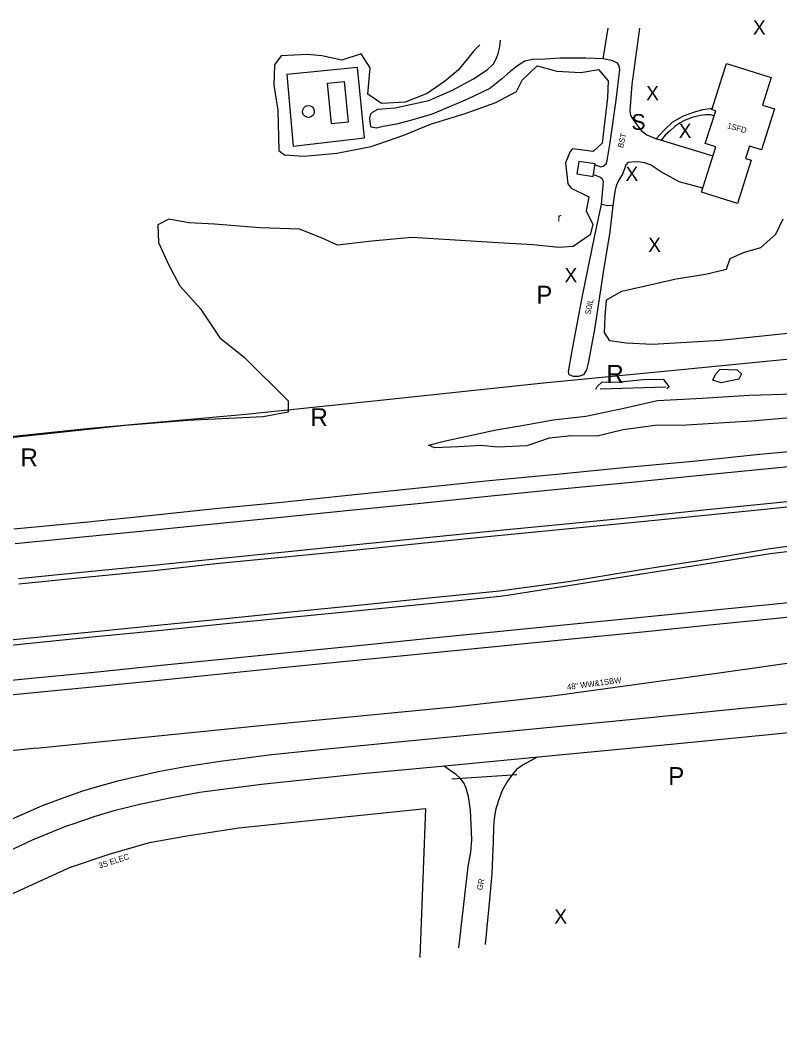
# Model space of a CAD drawing. Extents: x 2030130 to 2036320, y 723205 to 762423.
# Drawn here: x 2034070 to 2034598, y 726727 to 727435 of the extents above; entities that cross this region are included whole.
import ezdxf

# ---------------------------------------------------------------- set-up
doc = ezdxf.new("R2010")
doc.units = 0
for name, color, linetype in [('Draft_Bearing Label', 7, 'Continuous'), ('Draft_Station Cardinal Points', 7, 'Continuous'), ('Draft_Station Labels Major', 7, 'Continuous'), ('Draft_Station Tics Major', 7, 'Continuous'), ('Draft_Station Tics Minor', 7, 'Continuous'), ('Exist Terrain Model Ground Surface', 7, 'Continuous'), ('Old_Level_23', 7, 'Continuous'), ('Old_Level_28', 7, 'Continuous'), ('Prop Horizontal Alignment Ramp', 7, 'Continuous')]:
    doc.layers.add(name, color=color, linetype=linetype)

msp = doc.modelspace()

# ---------------------------------------------------------------- linework, layer by layer
at = {"layer": 'Draft_Station Labels Major'}
for points in [[(2034469.85, 727334.14), (2034473.89, 727332.82), (2034475.44, 727333.2), (2034476.51, 727333.91), (2034477.55, 727334.81), (2034478.22, 727337.13), (2034480.32, 727349.72), (2034484.5, 727379.19), (2034487.2, 727400.43), (2034486.69, 727402.99), (2034485.5, 727404.89), (2034483.25, 727406.08), (2034481.25, 727406.73), (2034475.4, 727408), (2034478.99, 727429.28)], [(2034500.85, 727429.34), (2034495.5, 727390.07), (2034493.98, 727371.73), (2034494.45, 727368.46), (2034496.4, 727365.63), (2034498.5, 727362.56), (2034502.07, 727357.95), (2034505.96, 727354.91), (2034511.95, 727352.45), (2034517.46, 727350.76), (2034551.97, 727340.32)], [(2034475.4, 727408), (2034463.47, 727408.38), (2034445.57, 727408.36), (2034435.16, 727407.79), (2034426.24, 727407.52), (2034421.06, 727406.44), (2034416.49, 727403.64), (2034410.78, 727399.1), (2034404.72, 727393.76), (2034396.55, 727387.38), (2034381.12, 727379.8), (2034356.45, 727369.36), (2034341.31, 727365.07), (2034331.58, 727362.53), (2034322.33, 727360.82), (2034317.62, 727359.67), (2034313.95, 727360.37), (2034313.38, 727362.41), (2034313.08, 727366.4), (2034313.76, 727369.74), (2034314.83, 727370.9), (2034318.68, 727372.84), (2034330.57, 727373.91), (2034354.06, 727378.91), (2034370.63, 727386.12), (2034385.13, 727393.97), (2034394.64, 727400.38), (2034399.24, 727404.53), (2034401.24, 727408.55), (2034402.26, 727411.74), (2034403.42, 727416.36), (2034404, 727420.97)], [(2034544.84, 727317.77), (2034528.38, 727322.25), (2034515.34, 727329.54), (2034508.45, 727334.06), (2034504.18, 727335.52), (2034500.08, 727336.16), (2034495.36, 727336.03), (2034492.58, 727335.76), (2034491.39, 727334.01), (2034490.54, 727332.05), (2034488.87, 727327.5), (2034486.27, 727323.15), (2034484.49, 727319.42), (2034483.68, 727315.61), (2034482.32, 727305.86), (2034478.84, 727305.49), (2034474.38, 727306.48), (2034475.69, 727322.37), (2034474.88, 727324.25), (2034473.13, 727325.5), (2034470.96, 727326.52), (2034468.78, 727327.11)], [(2034482.32, 727305.86), (2034480.25, 727287.32), (2034475.64, 727260.8), (2034469.48, 727219.32), (2034465.13, 727195.9), (2034463.97, 727191.28), (2034461.72, 727187.74), (2034458.33, 727186.69), (2034454.83, 727186.58), (2034451.87, 727187.75), (2034451.47, 727190), (2034453.96, 727204.56), (2034460.99, 727241.61), (2034469.74, 727284.88), (2034474.38, 727306.48)], [(2034065.11, 727080.41), (2034114.18, 727085.18), (2034159.64, 727089.79), (2034205.29, 727094.58), (2034249.28, 727098.81), (2034298.01, 727103.82), (2034347.16, 727108.96), (2034396.1, 727113.99), (2034445.48, 727118.71), (2034494.51, 727123.53), (2034540.56, 727127.91), (2034584.47, 727132.47), (2034632.87, 727136.76), (2034676.94, 727141.51), (2034722.09, 727145.88), (2034766.08, 727150.11), (2034812.33, 727155.08), (2034858.21, 727159.84), (2034888.24, 727162.54), (2034901.82, 727164.97), (2034916.41, 727170.63), (2034924.74, 727177.21), (2034929.69, 727189.85), (2034928.36, 727204.72)], [(2034065.93, 727070.12), (2034115.2, 727074.96), (2034160.49, 727079.46), (2034206.49, 727084.03), (2034251, 727088.47), (2034299.16, 727093.36), (2034348.43, 727098.29), (2034397.49, 727103.32), (2034446.31, 727108.22), (2034495.24, 727113.02), (2034541.05, 727117.58), (2034585.89, 727121.96), (2034633.87, 727126.74)], [(2034068.46, 727041.99), (2034117, 727046.94), (2034162.54, 727051.49), (2034207.98, 727056.52), (2034253.92, 727060.83), (2034301.72, 727065.65), (2034351.04, 727070.6), (2034399.56, 727075.53), (2034447.29, 727080.16), (2034497.37, 727085.09), (2034544.15, 727089.69), (2034587.77, 727094.04), (2034634.61, 727098.91), (2034679.17, 727103.19), (2034723.67, 727107.78), (2034769.24, 727112.21), (2034815.05, 727116.68), (2034860.82, 727121.08), (2034907.36, 727125.6), (2034927.3, 727127.18), (2034954.39, 727123.96), (2034963.41, 727122.83), (2034968.23, 727121), (2034968.86, 727119.68)], [(2034068.39, 727045.81), (2034116.83, 727050.61), (2034162, 727055.1), (2034207.66, 727059.77), (2034253.91, 727064.46), (2034301.41, 727069.22), (2034350.05, 727074.07), (2034398.98, 727078.95), (2034446.91, 727083.71), (2034497.05, 727088.65), (2034543.32, 727093.34), (2034587.33, 727097.77), (2034633.71, 727102.43)], [(2034025.26, 726999.38), (2034074.09, 727004.22), (2034121.41, 727008.89), (2034167.51, 727013.49), (2034212.61, 727017.88), (2034257.74, 727022.58), (2034304.93, 727027.33), (2034354.43, 727032.28), (2034403.23, 727037.18), (2034451.44, 727043.68), (2034500.54, 727051.92), (2034548.23, 727059.39), (2034591.81, 727066.61), (2034638.18, 727072.74)], [(2034025.48, 726995.5), (2034074.11, 727000.46), (2034121.82, 727005.27), (2034167.82, 727009.9), (2034212.93, 727014.39), (2034258.03, 727018.87), (2034305.11, 727023.52), (2034354.59, 727028.47), (2034403.42, 727033.39), (2034410.21, 727034.33), (2034451.41, 727040.91), (2034500.85, 727048.75), (2034548.22, 727056.21), (2034591.76, 727063.29), (2034638.43, 727068.84)], [(2034307.24, 726999.43), (2034356.84, 727004.45), (2034406.28, 727009.3), (2034452.81, 727013.89), (2034502.16, 727018.82), (2034550.88, 727023.74), (2034595.46, 727028.17), (2034641.07, 727032.82), (2034684.61, 727037.18), (2034729.52, 727041.63), (2034774.89, 727046.13), (2034819.08, 727050.5), (2034865.64, 727055.21), (2034912.23, 727059.85), (2034960.25, 727064.7), (2035005.43, 727069.15)], [(2034029.29, 726961.54), (2034076.69, 726966.05), (2034124.58, 726970.8), (2034170.82, 726975.48), (2034215.97, 726980.04), (2034261.31, 726984.82), (2034308.3, 726989.33), (2034357.75, 726994.14), (2034407.05, 726999.09), (2034453.5, 727003.73), (2034502.96, 727008.69), (2034552.18, 727013.64), (2034596.47, 727018.1), (2034642.31, 727022.98), (2034686.47, 727027.2), (2034731.1, 727031.69), (2034775.53, 727036.01), (2034820.01, 727040.42), (2034866.86, 727045.17), (2034912.58, 727049.64), (2034961.1, 727054.42), (2035006.09, 727059.13)], [(2034028.47, 726971.41), (2034075.13, 726976.03), (2034123.42, 726980.84), (2034169.95, 726985.53), (2034214.61, 726990.05), (2034260.27, 726994.74), (2034307.24, 726999.43)], [(2034100.02, 726893.21), (2034113.19, 726897.73), (2034127.48, 726902.01), (2034138.45, 726904.91), (2034153.6, 726908.58), (2034166.83, 726911.5), (2034184.54, 726914.84), (2034208.76, 726918.46), (2034244.76, 726923.08), (2034281.05, 726926.95), (2034335.04, 726932.09), (2034407.37, 726939.15), (2034496.46, 726947.83), (2034567.94, 726954.98), (2034652.73, 726963.38), (2034739.31, 726971.94), (2034824.38, 726980.7), (2034903.5, 726988.86), (2034964.59, 726994.74)], [(2034965.29, 726974.83), (2034889.6, 726967.15), (2034805.97, 726958.77), (2034704.1, 726948.2), (2034616.57, 726939.46), (2034525.2, 726930.45), (2034442.43, 726922.42), (2034365.29, 726915.02), (2034307.64, 726909.57), (2034237.47, 726902.31), (2034194.3, 726896.56), (2034172.53, 726892.46), (2034152.78, 726888.36), (2034134.81, 726883.95), (2034120.78, 726879.64), (2034106.93, 726874.9), (2034101.08, 726873.01)], [(2034429.65, 726921.2), (2034419.87, 726915.98), (2034415.15, 726912.75), (2034411.9, 726908.66), (2034408.77, 726904.65), (2034405.23, 726898.14), (2034402.67, 726891.03), (2034400.63, 726884.43), (2034399.56, 726878.41), (2034399.1, 726872.66), (2034398.85, 726862.08), (2034398.37, 726851.73), (2034397.92, 726840.09), (2034396.44, 726822.11), (2034393.43, 726790.74)], [(2034375.08, 726788.34), (2034381.58, 726845.05), (2034383.34, 726854.98), (2034383.99, 726863.86), (2034383.67, 726874.37), (2034383.09, 726884.4), (2034381.61, 726893.86), (2034380.04, 726899.75), (2034378.48, 726903.51), (2034375.95, 726906.75), (2034373.18, 726909.26), (2034370.6, 726910.76), (2034364.65, 726914.96)], [(2033812.11, 726727.17), (2033828.95, 726734.67), (2033849.51, 726744.64), (2033871.89, 726757.68), (2033893.57, 726771.7), (2033914.82, 726786.38), (2033937.73, 726803.32), (2033961.25, 726820.08), (2033982.38, 726834.35), (2034000.03, 726845.41), (2034021.37, 726857.68), (2034043.29, 726868.71), (2034063.4, 726878.13), (2034085.11, 726887.6), (2034100.02, 726893.21)], [(2034101.08, 726873.01), (2034077.84, 726863.35), (2034051.94, 726851.31), (2034025.37, 726837.58), (2033999.28, 726821.86), (2033977.92, 726808.19), (2033952.29, 726788.94), (2033920.71, 726765.94), (2033902.13, 726753.17), (2033889.02, 726744.27), (2033873.65, 726735.09), (2033859.69, 726727.5)]]:
    msp.add_lwpolyline(points, dxfattribs=at)
at = {"layer": 'Draft_Station Tics Major'}
msp.add_line((2034519.18, 727179.08), (2034473.32, 727177.8), dxfattribs=at)
for points in [[(2034389.53, 727417.76), (2034385.49, 727413.61), (2034380.84, 727407.73), (2034374.54, 727400.17), (2034365.08, 727392.23), (2034352.88, 727383.76), (2034337.54, 727377.84), (2034321.16, 727376.79), (2034311.65, 727383.37), (2034313.12, 727401.73), (2034307.02, 727411.35), (2034293.59, 727407), (2034279.51, 727410.14), (2034269.29, 727411.06), (2034251.31, 727410), (2034246.69, 727403.81), (2034246.19, 727389.67), (2034248.92, 727372.15), (2034249.73, 727343.98), (2034253.64, 727341.06), (2034267.23, 727340.23), (2034290.07, 727342.33), (2034313.95, 727346.92), (2034336.73, 727354.77), (2034355.18, 727362.41), (2034379.42, 727369.8), (2034400.79, 727377.61), (2034415.21, 727385.27), (2034419.18, 727393.05), (2034429.53, 727403.09), (2034443.25, 727399.28), (2034460.03, 727398.55), (2034472.2, 727400.58), (2034478.92, 727392.71), (2034478.52, 727380.82), (2034476.11, 727361.39), (2034474.72, 727349.25), (2034468.61, 727343.39), (2034454.08, 727345.21), (2034452.46, 727343.37), (2034449.19, 727335.55), (2034450.99, 727320.76), (2034453.33, 727317.83), (2034465.42, 727311.9), (2034463.7, 727301.96), (2034468.38, 727292.49), (2034466.37, 727285.39), (2034454.71, 727277.18), (2034444.55, 727276.57), (2034426.85, 727278.43), (2034402.2, 727279.63), (2034376.14, 727281.29), (2034342.15, 727283.52), (2034314.39, 727280.81), (2034290.46, 727278.2), (2034279.83, 727282.91), (2034263.97, 727289.15), (2034236.27, 727290.1), (2034204.71, 727292.82), (2034187.01, 727293.65), (2034173.06, 727296.29), (2034165.24, 727292.26), (2034165.86, 727279.86), (2034172.79, 727264.58), (2034180.61, 727249.87), (2034195.02, 727233.66), (2034208.44, 727213.48), (2034225.57, 727200.04), (2034256.23, 727169.7), (2034256.19, 727161.69), (2034238.73, 727158.52), (2034185.89, 727155.81), (2034142.74, 727152.37), (2034062.7, 727143.95)], [(2034615.4, 727217.62), (2034557.13, 727211.69), (2034509.75, 727208.81), (2034491.51, 727209.9), (2034480.05, 727211.5), (2034476.52, 727217.28), (2034476.88, 727228.45), (2034477.84, 727239.96), (2034488.59, 727246.15), (2034502.87, 727249.24), (2034526.26, 727254.67), (2034546.67, 727257.82), (2034561.47, 727261.3), (2034563.93, 727268.89), (2034573.16, 727272.91), (2034585.28, 727276.38), (2034595.78, 727285.73), (2034600.79, 727296.52)], [(2034556.76, 727191.69), (2034568.78, 727191.24), (2034571.87, 727188.49), (2034569.97, 727184.67), (2034557.68, 727182.14), (2034551.94, 727184.05), (2034553.89, 727188.52), (2034556.66, 727191.48)], [(2034470.48, 727177.78), (2034471.42, 727179.69), (2034474.57, 727182.7)], [(2034474.51, 727182.63), (2034487.27, 727182.98), (2034503.32, 727184.56), (2034517.27, 727184.61), (2034521.49, 727179.37), (2034519.9, 727177.95)], [(2034635.73, 727160.42), (2034578.87, 727155.49), (2034533.46, 727152.73), (2034511.75, 727152.37), (2034489.4, 727149.43), (2034471.38, 727145.04), (2034453.43, 727145.27), (2034437.91, 727143.5), (2034422.31, 727138.19), (2034402.07, 727137.3), (2034390.34, 727138.49), (2034374.71, 727137.59), (2034357.97, 727136.88), (2034353.85, 727138.68), (2034365.68, 727141.86), (2034400.89, 727149.51), (2034417.72, 727152.09), (2034440.74, 727156.45), (2034463.47, 727158.92), (2034489.85, 727164.52), (2034513.3, 727169.96), (2034544.34, 727171.53), (2034577.5, 727173.49), (2034608.28, 727174.46)]]:
    msp.add_lwpolyline(points, dxfattribs=at)
at = {"layer": 'Draft_Station Tics Minor'}
msp.add_line((2034370.09, 726906.27), (2034415.26, 726909.1), dxfattribs=at)
at = {"layer": 'Exist Terrain Model Ground Surface'}
for points in [[(2034544.02, 727315.16), (2034553.96, 727346.61), (2034546.66, 727348.92), (2034553.87, 727371.71), (2034551.26, 727372.53), (2034561.47, 727404.81), (2034592.49, 727395), (2034586.39, 727375.72), (2034594.8, 727373.06), (2034585.76, 727344.44), (2034577.36, 727347.09), (2034574.66, 727338.55), (2034578.66, 727337.29), (2034569.15, 727307.21)], [(2034295.03, 727392.12), (2034297.85, 727363.95), (2034286.22, 727362.79), (2034283.41, 727390.96)], [(2034469.95, 727334.77), (2034458.55, 727336.5), (2034457.22, 727327.77), (2034468.62, 727326.04)]]:
    msp.add_lwpolyline(points, close=True, dxfattribs=at)
for points in [[(2034309.34, 727352.64), (2034304.38, 727401.83), (2034255.23, 727397.08), (2034259.51, 727347.16), (2034309.24, 727352.89)], [(2034512.44, 727352.3), (2034517.93, 727358.22), (2034524.07, 727364.02), (2034531.52, 727368.17), (2034539.39, 727371.08), (2034545.03, 727372.55), (2034551.6, 727373.6)], [(2034552.8, 727368.33), (2034550.33, 727368.93), (2034546.89, 727369.02), (2034543.13, 727368.56), (2034537.43, 727367.02), (2034532.53, 727365.25), (2034528.76, 727363.24), (2034525.37, 727360.82), (2034522.35, 727358.05), (2034518.74, 727354.76), (2034515.8, 727351.27)], [(2034878.49, 727250.18), (2034876.25, 727243.37), (2034850.21, 727223.03), (2034766.68, 727214.38), (2034624.66, 727200.53), (2034525.2, 727190.87), (2034433.9, 727181.91), (2034318.13, 727169.55), (2034226.56, 727160.17), (2034115.95, 727150.11), (2034053.6, 727143.54)], [(2034080.59, 726927.58), (2034239.08, 726943.54), (2034371.22, 726956.33), (2034441.82, 726964.29), (2034557.85, 726980.21), (2034679.1, 726997.43), (2034757.65, 727008.11), (2034853.32, 727015.97), (2034965.98, 727025.07)], [(2034080.59, 726927.58), (2034012.83, 726920.33), (2034014.93, 726890.92), (2033898.46, 726877.31), (2033757.43, 726863.13), (2033660.43, 726856.18), (2033539.78, 726843.39), (2033452.23, 726834.45), (2033327.61, 726822.42), (2033251.82, 726813.91), (2033229.8, 726848.61), (2033218.99, 726847.12), (2033214.59, 726850.71), (2033179.77, 726848.21), (2033018.11, 726832.31), (2032917.89, 726821.36), (2032840.99, 726814.69), (2032765.32, 726806.44), (2032687.65, 726799.42), (2032610.44, 726790.66), (2032519.7, 726780.77), (2032297.67, 726759.05)], [(2034105.17, 726844.97), (2034131.35, 726853.62), (2034159.46, 726861.86), (2034185.56, 726866.49), (2034221.65, 726871.96), (2034275.4, 726877.52), (2034351.69, 726885.53), (2034350.07, 726842.87), (2034347.81, 726781.63)], [(2034105.17, 726844.97), (2034053.23, 726821.16), (2034024.96, 726804.56), (2033982.48, 726776.49), (2033936.22, 726741.92)]]:
    msp.add_lwpolyline(points, dxfattribs=at)
msp.add_ellipse((2034270.22, 727371.3), major_axis=(-0.5, 4.1), ratio=0.999893, dxfattribs=at)

# ---------------------------------------------------------------- texts
at = {"layer": 'Draft_Bearing Label'}
msp.add_text('r', height=6, dxfattribs=at).set_placement((2034443.72, 727294.39))
at = {"layer": 'Draft_Station Cardinal Points'}
msp.add_text('S', height=11, dxfattribs=at).set_placement((2034495.21, 727358.48))
at = {"layer": 'Draft_Station Tics Major'}
for p in [(2034579.81, 727424.83), (2034505.43, 727379.1), (2034528.09, 727352.8), (2034491.04, 727322.87), (2034506.83, 727273.37), (2034448.58, 727252.19), (2034441.43, 726805.24)]:
    msp.add_text('X', height=10, dxfattribs=at).set_placement(p)
at = {"layer": 'Old_Level_23'}
for s, rotation, p in [('BST', 76.33598, (2034489.31, 727345.54)), ('S0IL', 79.06446, (2034466.74, 727229.46)), ('GR', 77.48573, (2034391.2, 726828.33))]:
    msp.add_text(s, height=4, rotation=rotation, dxfattribs=at).set_placement(p)
at = {"layer": 'Old_Level_28'}
for s, rotation, p in [('1SFD', 344.66422, (2034561.6, 727359.68)), ('48" WW&1SBW', 7.58707, (2034450.57, 726968.13)), ('3S ELEC', 17.88339, (2034124.82, 726843.61))]:
    msp.add_text(s, height=4, rotation=rotation, dxfattribs=at).set_placement(p)
at = {"layer": 'Prop Horizontal Alignment Ramp'}
for s, p in [('P', (2034428.93, 727237.31)), ('R', (2034477.75, 727182.16)), ('R', (2034271.68, 727151.99)), ('R', (2034069.7, 727123.92)), ('P', (2034520.86, 726901.84))]:
    msp.add_text(s, height=12.5, dxfattribs=at).set_placement(p)

doc.saveas('drawing.dxf')
